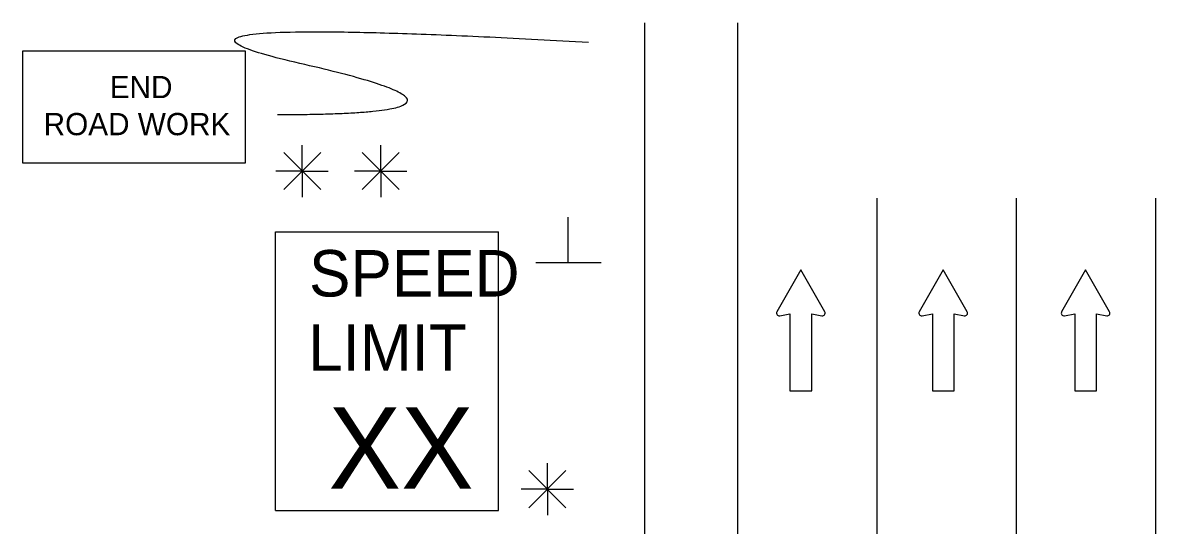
# Model space of a CAD drawing. Extents: x 16728 to 18479, y 5752 to 6927.
# Drawn here: x 16734.8 to 16930, y 6840.1 to 6926.7 of the extents above; entities that cross this region are included whole.
import ezdxf

# ---------------------------------------------------------------- set-up
doc = ezdxf.new("R2010")
doc.units = 0
for name, color, linetype in [('ALI_LEGAL_EX', 7, 'Continuous'), ('MT_SCRATCH_LEVEL_E', 7, 'Continuous'), ('PAVT_EDGE_EX', 7, 'Continuous'), ('TRAFFIC_SIGNS_PR', 7, 'Continuous'), ('TYPICAL_TEXT_DIMEN_PR', 7, 'Continuous')]:
    doc.layers.add(name, color=color, linetype=linetype)

msp = doc.modelspace()

# ---------------------------------------------------------------- linework, layer by layer
at = {"layer": 'ALI_LEGAL_EX'}
for p, q in [((16881.97, 6876.43), (16881.97, 5996.39)), ((16905.97, 6876.43), (16905.97, 5996.39)), ((16929.97, 6876.43), (16929.97, 5996.39))]:
    msp.add_line(p, q, dxfattribs=at)
for points in [[(16881.97, 6896.46), (16881.97, 6871.46)], [(16905.97, 6896.46), (16905.97, 6871.46)], [(16929.97, 6896.46), (16929.97, 6871.46)]]:
    msp.add_lwpolyline(points, dxfattribs=at)
at = {"layer": 'MT_SCRATCH_LEVEL_E'}
for p, q in [((16868.88, 6884.13), (16864.76, 6876.89)), ((16873.02, 6876.89), (16868.88, 6884.13)), ((16893.4, 6884.13), (16889.29, 6876.89)), ((16897.55, 6876.89), (16893.4, 6884.13)), ((16917.93, 6884.13), (16913.82, 6876.89)), ((16922.08, 6876.89), (16917.93, 6884.13)), ((16865.25, 6876.2), (16867.02, 6876.52)), ((16867.02, 6876.52), (16867.02, 6863.26)), ((16870.77, 6863.26), (16870.77, 6876.52)), ((16870.77, 6876.52), (16872.54, 6876.2)), ((16889.78, 6876.2), (16891.55, 6876.52)), ((16891.55, 6876.52), (16891.55, 6863.26)), ((16895.3, 6863.26), (16895.3, 6876.52)), ((16895.3, 6876.52), (16897.07, 6876.2)), ((16914.31, 6876.2), (16916.08, 6876.52)), ((16916.08, 6876.52), (16916.08, 6863.26)), ((16919.82, 6863.26), (16919.82, 6876.52)), ((16919.82, 6876.52), (16921.6, 6876.2)), ((16867.02, 6863.26), (16870.77, 6863.26)), ((16891.55, 6863.26), (16895.3, 6863.26)), ((16916.08, 6863.26), (16919.82, 6863.26))]:
    msp.add_line(p, q, dxfattribs=at)
for centre, start, end in [((16865.17, 6876.66), 150.4248, 279.9638), ((16872.61, 6876.66), 260.0362, 29.7731), ((16889.7, 6876.66), 150.4248, 279.9638), ((16897.14, 6876.66), 260.0362, 29.7731), ((16914.23, 6876.66), 150.4248, 279.9638), ((16921.67, 6876.66), 260.0362, 29.7731)]:
    msp.add_arc(centre, 0.463, start, end, dxfattribs=at)
at = {"layer": 'PAVT_EDGE_EX'}
for p, q in [((16841.97, 6926.69), (16841.97, 6016.42)), ((16857.97, 6926.69), (16857.97, 6016.42))]:
    msp.add_line(p, q, dxfattribs=at)
at = {"layer": 'TRAFFIC_SIGNS_PR'}
for p, q in [((16778.4, 6890.66), (16816.8, 6890.66)), ((16778.4, 6842.66), (16778.4, 6890.66)), ((16816.8, 6842.66), (16816.8, 6890.66)), ((16778.4, 6842.66), (16816.8, 6842.66))]:
    msp.add_line(p, q, dxfattribs=at)
msp.add_lwpolyline([(16734.84, 6902.56), (16773.24, 6902.56), (16773.24, 6921.76), (16734.84, 6921.76)], close=True, dxfattribs=at)
msp.add_open_spline([(16778.76, 6910.87), (16821.27, 6910.87), (16744.75, 6928.28), (16832.3, 6923.34)], degree=2, dxfattribs=at)
at = {"layer": 'TYPICAL_TEXT_DIMEN_PR'}
for p, q in [((16783.01, 6901.14), (16783.01, 6905.59)), ((16796.52, 6901.14), (16796.52, 6905.59)), ((16779.83, 6904.32), (16786.2, 6897.95)), ((16786.2, 6904.32), (16779.83, 6897.95)), ((16793.33, 6904.32), (16799.71, 6897.95)), ((16799.71, 6904.32), (16793.33, 6897.95)), ((16783.01, 6901.14), (16778.48, 6901.14)), ((16783.01, 6901.14), (16786.2, 6901.14)), ((16783.01, 6901.14), (16787.49, 6901.14)), ((16783.01, 6901.14), (16783.01, 6896.64)), ((16796.52, 6901.14), (16791.99, 6901.14)), ((16796.52, 6901.14), (16799.71, 6901.14)), ((16796.52, 6901.14), (16801, 6901.14)), ((16796.52, 6901.14), (16796.52, 6896.64)), ((16828.84, 6885.41), (16828.84, 6893.19)), ((16823.22, 6885.41), (16834.47, 6885.41)), ((16822.05, 6849.54), (16828.42, 6843.16)), ((16828.42, 6849.54), (16822.05, 6843.16)), ((16825.23, 6846.35), (16825.23, 6850.81)), ((16825.23, 6846.35), (16820.7, 6846.35)), ((16825.23, 6846.35), (16828.42, 6846.35)), ((16825.23, 6846.35), (16829.71, 6846.35)), ((16825.23, 6846.35), (16825.23, 6841.85))]:
    msp.add_line(p, q, dxfattribs=at)

# ---------------------------------------------------------------- texts
at = {"layer": 'TRAFFIC_SIGNS_PR'}
for s, height, p in [('END', 3.831, (16749.84, 6913.69)), ('ROAD WORK', 3.831, (16738.45, 6907.31)), ('SPEED', 8, (16784.17, 6879.53)), ('LIMIT', 8, (16784.01, 6866.73)), ('XX', 14.031, (16787.51, 6846.42))]:
    msp.add_text(s, height=height, dxfattribs=at).set_placement(p)

doc.saveas('drawing.dxf')
